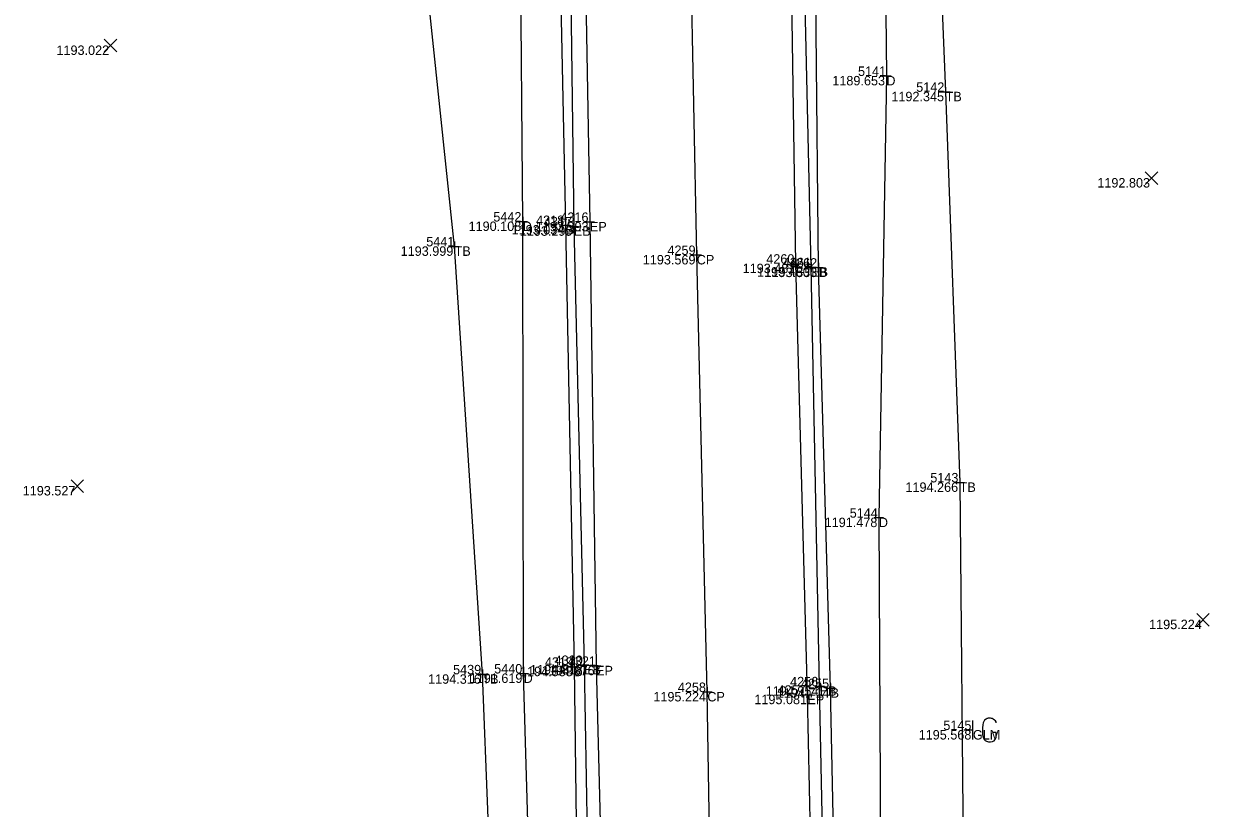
# Model space of a CAD drawing. Extents: x 2044996 to 2050343, y 455232 to 458054.
# Drawn here: x 2047545.2 to 2047670.6, y 457700.8 to 457783.9 of the extents above; entities that cross this region are included whole.
import ezdxf

# ---------------------------------------------------------------- set-up
doc = ezdxf.new("R2010")
doc.units = 0
for name, color, linetype in [('DR_X_Ditch', 7, 'Continuous'), ('DT_X_Contour_Minor', 7, 'Continuous'), ('DT_X_Contour_Text', 7, 'Continuous'), ('DT_X_Spot_Elev', 7, 'Continuous'), ('DT_X_Triangles', 7, 'Continuous'), ('DT_X_Void', 7, 'Continuous'), ('PV_X_COP', 7, 'Continuous'), ('PV_X_EOP', 7, 'Continuous'), ('PV_X_Shoulder_Aggregate', 7, 'Continuous'), ('SV_X_Break_Lines', 7, 'Continuous'), ('SV_X_Top_of_Bank', 7, 'Continuous'), ('UT_X_Gas_Cells', 7, 'Continuous')]:
    doc.layers.add(name, color=color, linetype=linetype)

msp = doc.modelspace()

# ---------------------------------------------------------------- linework, layer by layer
at = {"layer": 'DR_X_Ditch'}
for points in [[(2047603.88, 457240.71), (2047604.35, 457290.98), (2047605.27, 457322.96), (2047604.86, 457368.19), (2047603.19, 457417.51), (2047602.95, 457459.42), (2047602.66, 457501.84), (2047602.14, 457544.04), (2047601.08, 457584.06), (2047599.69, 457624.96), (2047599.4, 457669.27), (2047598.07, 457715.09), (2047597.97, 457762.92), (2047597.74, 457792.66), (2047596.26, 457838.2), (2047595.41, 457854.46)], [(2047635.93, 457828.45), (2047636.46, 457778.33), (2047635.67, 457731.58), (2047635.87, 457688.92), (2047636.59, 457650.58), (2047637.14, 457615.31), (2047638.36, 457574.87), (2047638.82, 457526.07), (2047639.21, 457482.92), (2047639.9, 457443.66), (2047641.24, 457398.66), (2047642.28, 457344.51), (2047644.03, 457300.89), (2047646.18, 457262.24), (2047646.96, 457237.04), (2047650.76, 457191.22), (2047650.42, 457143.89), (2047649.26, 457104.81), (2047651.9, 457052.9), (2047656.34, 457022.85)]]:
    msp.add_lwpolyline(points, dxfattribs=at)
at = {"layer": 'DT_X_Spot_Elev'}
for p, q in [((2047553.68, 457780.88), (2047555.02, 457782.22)), ((2047553.68, 457782.22), (2047555.02, 457780.88)), ((2047663.85, 457766.85), (2047665.18, 457768.19)), ((2047663.85, 457768.19), (2047665.18, 457766.85)), ((2047550.16, 457734.26), (2047551.5, 457735.6)), ((2047550.16, 457735.6), (2047551.5, 457734.26)), ((2047669.31, 457720.11), (2047670.64, 457721.45)), ((2047669.31, 457721.45), (2047670.64, 457720.11))]:
    msp.add_line(p, q, dxfattribs=at)
at = {"layer": 'DT_X_Void'}
for p, q in [((2047635.96, 457778.33), (2047636.96, 457778.33)), ((2047636.46, 457778.83), (2047636.46, 457777.83)), ((2047636.46, 457778.33), (2047636.46, 457778.33)), ((2047642.73, 457777.15), (2047642.73, 457776.15)), ((2047642.23, 457776.65), (2047643.23, 457776.65)), ((2047642.73, 457776.65), (2047642.73, 457776.65)), ((2047597.97, 457763.42), (2047597.97, 457762.42)), ((2047605.08, 457763.38), (2047605.08, 457762.38)), ((2047597.47, 457762.92), (2047598.47, 457762.92)), ((2047597.97, 457762.92), (2047597.97, 457762.92)), ((2047602.01, 457762.55), (2047603.01, 457762.55)), ((2047602.51, 457763.05), (2047602.51, 457762.05)), ((2047602.51, 457762.55), (2047602.51, 457762.55)), ((2047602.87, 457762.41), (2047603.87, 457762.41)), ((2047603.37, 457762.91), (2047603.37, 457761.91)), ((2047603.37, 457762.41), (2047603.37, 457762.41)), ((2047604.58, 457762.88), (2047605.58, 457762.88)), ((2047605.08, 457762.88), (2047605.08, 457762.88)), ((2047590.76, 457760.79), (2047590.76, 457759.79)), ((2047590.26, 457760.29), (2047591.26, 457760.29)), ((2047590.76, 457760.29), (2047590.76, 457760.29)), ((2047616.39, 457759.88), (2047616.39, 457758.88)), ((2047615.89, 457759.38), (2047616.89, 457759.38)), ((2047616.39, 457759.38), (2047616.39, 457759.38)), ((2047626.37, 457758.46), (2047627.37, 457758.46)), ((2047626.87, 457758.96), (2047626.87, 457757.96)), ((2047626.87, 457758.46), (2047626.87, 457758.46)), ((2047628.5, 457758.59), (2047628.5, 457757.59)), ((2047629.28, 457758.54), (2047629.28, 457757.54)), ((2047628, 457758.09), (2047629, 457758.09)), ((2047628.5, 457758.09), (2047628.5, 457758.09)), ((2047628.78, 457758.04), (2047629.78, 457758.04)), ((2047629.28, 457758.04), (2047629.28, 457758.04)), ((2047644.22, 457735.81), (2047644.22, 457734.81)), ((2047643.72, 457735.31), (2047644.72, 457735.31)), ((2047644.22, 457735.31), (2047644.22, 457735.31)), ((2047635.67, 457732.08), (2047635.67, 457731.08)), ((2047635.17, 457731.58), (2047636.17, 457731.58)), ((2047635.67, 457731.58), (2047635.67, 457731.58)), ((2047598.07, 457715.59), (2047598.07, 457714.59)), ((2047602.92, 457715.8), (2047603.92, 457715.8)), ((2047603.42, 457716.3), (2047603.42, 457715.3)), ((2047603.42, 457715.8), (2047603.42, 457715.8)), ((2047603.97, 457715.99), (2047604.97, 457715.99)), ((2047604.47, 457716.49), (2047604.47, 457715.49)), ((2047604.47, 457715.99), (2047604.47, 457715.99)), ((2047605.24, 457715.9), (2047606.24, 457715.9)), ((2047605.74, 457716.4), (2047605.74, 457715.4)), ((2047605.74, 457715.9), (2047605.74, 457715.9)), ((2047593.2, 457715), (2047594.2, 457715)), ((2047593.7, 457715.5), (2047593.7, 457714.5)), ((2047593.7, 457715), (2047593.7, 457715)), ((2047597.57, 457715.09), (2047598.57, 457715.09)), ((2047598.07, 457715.09), (2047598.07, 457715.09)), ((2047617.01, 457713.13), (2047618.01, 457713.13)), ((2047617.51, 457713.63), (2047617.51, 457712.63)), ((2047617.51, 457713.13), (2047617.51, 457713.13)), ((2047628.1, 457713.34), (2047628.1, 457712.34)), ((2047628.9, 457713.73), (2047629.9, 457713.73)), ((2047629.4, 457714.23), (2047629.4, 457713.23)), ((2047629.4, 457713.73), (2047629.4, 457713.73)), ((2047630.06, 457713.53), (2047631.06, 457713.53)), ((2047630.56, 457714.03), (2047630.56, 457713.03)), ((2047630.56, 457713.53), (2047630.56, 457713.53)), ((2047627.6, 457712.84), (2047628.6, 457712.84)), ((2047628.1, 457712.84), (2047628.1, 457712.84))]:
    msp.add_line(p, q, dxfattribs=at)
at = {"layer": 'PV_X_COP'}
msp.add_lwpolyline([(2047630.7, 457032.77), (2047629.57, 457079.46), (2047628.83, 457121.31), (2047627.83, 457168.37), (2047627.23, 457213.89), (2047626.35, 457261.41), (2047625.27, 457313.88), (2047624.14, 457367.69), (2047623.14, 457414.96), (2047622.16, 457463.48), (2047621.21, 457510.6), (2047620.34, 457561.9), (2047619.47, 457614.83), (2047618.33, 457662.23), (2047617.51, 457713.13), (2047616.39, 457759.38), (2047615.44, 457807.27), (2047614.41, 457854.52), (2047614.29, 457881.56), (2047613.16, 457931.14), (2047612.06, 457984.05), (2047611.48, 458032.26), (2047610.91, 458052.26)], dxfattribs=at)
at = {"layer": 'PV_X_EOP'}
for p, q in [((2047626.87, 457758.46), (2047626.15, 457807.46)), ((2047604.32, 457806.33), (2047605.08, 457762.88)), ((2047605.08, 457762.88), (2047605.74, 457715.9)), ((2047628.1, 457712.84), (2047626.87, 457758.46)), ((2047605.74, 457715.9), (2047606.92, 457669.5)), ((2047629.22, 457661.11), (2047628.1, 457712.84))]:
    msp.add_line(p, q, dxfattribs=at)
at = {"layer": 'PV_X_Shoulder_Aggregate'}
for p, q in [((2047602.79, 457806.21), (2047603.37, 457762.41)), ((2047603.37, 457762.41), (2047604.47, 457715.99)), ((2047604.47, 457715.99), (2047605.27, 457669.2))]:
    msp.add_line(p, q, dxfattribs=at)
msp.add_lwpolyline([(2047636.93, 457312.89), (2047635.93, 457367.47), (2047634.97, 457414.6), (2047633.92, 457462.12), (2047633.13, 457509.72), (2047632.17, 457560.26), (2047631.16, 457614.81), (2047630.46, 457661.29), (2047629.4, 457713.73), (2047628.5, 457758.09), (2047627.36, 457807.43), (2047627.48, 457822.09), (2047628.61, 457825.87), (2047628.68, 457844.07), (2047627.2, 457879.15), (2047626.26, 457880.5), (2047625.13, 457929.52), (2047623.96, 457984.29), (2047622.9, 458032.45), (2047622.9, 458052.72)], dxfattribs=at)
at = {"layer": 'SV_X_Break_Lines'}
for points in [[(2047600.59, 457854.75), (2047601.57, 457806.15), (2047602.51, 457762.55), (2047603.42, 457715.8), (2047604.03, 457669.25), (2047604.95, 457623.23), (2047606.04, 457575.98), (2047606.89, 457528.52), (2047606.36, 457485.08), (2047608.62, 457438.46), (2047609.61, 457393.11), (2047610.32, 457343.26)], [(2047638.13, 457312.9), (2047637.8, 457367.1), (2047636.31, 457414.94), (2047635.39, 457462.19), (2047634.84, 457510.57), (2047633.75, 457560.46), (2047632.44, 457614.37), (2047631.64, 457661.27), (2047630.56, 457713.53), (2047629.28, 457758.04), (2047628.78, 457808.04), (2047629.36, 457824.93)]]:
    msp.add_lwpolyline(points, dxfattribs=at)
at = {"layer": 'SV_X_Top_of_Bank'}
for points in [[(2047602.07, 457232.89), (2047595.37, 457236.81), (2047596.56, 457240.43), (2047601.59, 457243.99), (2047601.86, 457291.34), (2047601.11, 457323.06), (2047599.87, 457367.88), (2047599.04, 457416.36), (2047598.26, 457460), (2047598.65, 457502.28), (2047597.03, 457543.46), (2047596.32, 457583.97), (2047595.27, 457626.15), (2047595.52, 457669.28), (2047593.7, 457715), (2047590.76, 457760.29), (2047587.57, 457790.55), (2047585.9, 457853.96)], [(2047640.57, 457829.63), (2047642.73, 457776.65), (2047644.22, 457735.31), (2047644.62, 457692.67), (2047644.93, 457653.27), (2047648.25, 457619.87), (2047649.32, 457574.48), (2047650.08, 457529.2), (2047650.6, 457480.31), (2047651.65, 457447.12), (2047652.29, 457398.02), (2047653.83, 457346.33), (2047654.34, 457298.99), (2047654.68, 457261.41), (2047656.79, 457189.89), (2047656.98, 457146.62), (2047657.59, 457104.22), (2047658.54, 457057.89), (2047659.73, 457026.44)]]:
    msp.add_lwpolyline(points, dxfattribs=at)
at = {"layer": 'UT_X_Gas_Cells'}
for p, q in [((2047645.62, 457708.1), (2047645.62, 457710.1)), ((2047645.62, 457709.1), (2047644.67, 457709.1))]:
    msp.add_line(p, q, dxfattribs=at)
msp.add_lwpolyline([(2047648.09, 457709.86), (2047648.07, 457709.96), (2047648.01, 457710.06), (2047647.92, 457710.15), (2047647.78, 457710.27), (2047647.68, 457710.31), (2047647.6, 457710.33), (2047647.48, 457710.35), (2047647.25, 457710.35), (2047647.15, 457710.33), (2047647.09, 457710.31), (2047647.01, 457710.27), (2047646.85, 457710.15), (2047646.76, 457710.02), (2047646.7, 457709.86), (2047646.66, 457709.64), (2047646.62, 457709.33), (2047646.62, 457708.91), (2047646.64, 457708.58), (2047646.72, 457708.32), (2047646.83, 457708.09), (2047646.93, 457708.01), (2047647.05, 457707.93), (2047647.27, 457707.85), (2047647.48, 457707.85), (2047647.7, 457707.89), (2047647.78, 457707.93), (2047647.86, 457707.97), (2047647.94, 457708.05), (2047648.01, 457708.17), (2047648.09, 457708.34), (2047648.09, 457708.84), (2047647.68, 457708.84)], dxfattribs=at)

# ---------------------------------------------------------------- texts
at = {"layer": 'DT_X_Contour_Minor'}
for s, p in [('1193.022', (2047548.62, 457780.55)), ('1189.653', (2047630.74, 457777.33)), ('1192.345', (2047636.99, 457775.65)), ('1192.803', (2047658.79, 457766.52)), ('1190.108', (2047592.24, 457761.92)), ('1193.034', (2047596.8, 457761.55)), ('1193.299', (2047597.66, 457761.41)), ('1193.393', (2047599.36, 457761.88)), ('1193.999', (2047585.05, 457759.29)), ('1193.569', (2047610.68, 457758.38)), ('1193.481', (2047621.25, 457757.46)), ('1193.460', (2047622.77, 457757.09)), ('1193.333', (2047623.56, 457757.04)), ('1193.527', (2047545.05, 457733.93)), ('1194.266', (2047638.48, 457734.31)), ('1191.478', (2047629.93, 457730.58)), ('1195.224', (2047664.27, 457719.78)), ('1194.588', (2047597.69, 457714.8)), ('1194.818', (2047598.74, 457714.99)), ('1194.876', (2047600, 457714.9)), ('1194.316', (2047587.96, 457714)), ('1191.619', (2047592.36, 457714.09)), ('1195.224', (2047611.8, 457712.13)), ('1194.954', (2047623.69, 457712.73)), ('1194.714', (2047624.86, 457712.53)), ('1195.081', (2047622.49, 457711.84)), ('1195.568', (2047639.88, 457708.1))]:
    msp.add_text(s, height=1, dxfattribs=at).set_placement(p)
at = {"layer": 'DT_X_Contour_Text'}
for s, p in [('D', (2047636.46, 457777.33)), ('TB', (2047642.73, 457775.65)), ('D', (2047597.97, 457761.92)), ('B', (2047602.51, 457761.55)), ('EB', (2047603.37, 457761.41)), ('EP', (2047605.08, 457761.88)), ('TB', (2047590.76, 457759.29)), ('CP', (2047616.39, 457758.38)), ('EP', (2047626.87, 457757.46)), ('EB', (2047628.5, 457757.09)), ('B', (2047629.28, 457757.04)), ('TB', (2047644.22, 457734.31)), ('D', (2047635.67, 457730.58)), ('B', (2047603.42, 457714.8)), ('EB', (2047604.47, 457714.99)), ('EP', (2047605.74, 457714.9)), ('TB', (2047593.7, 457714)), ('D', (2047598.07, 457714.09)), ('CP', (2047617.51, 457712.13)), ('EB', (2047629.4, 457712.73)), ('B', (2047630.56, 457712.53)), ('EP', (2047628.1, 457711.84)), ('GLM', (2047645.62, 457708.1))]:
    msp.add_text(s, height=1, dxfattribs=at).set_placement(p)
at = {"layer": 'DT_X_Triangles'}
for s, p in [('5141', (2047633.46, 457778.33)), ('5142', (2047639.62, 457776.65)), ('5442', (2047594.86, 457762.92)), ('4318', (2047599.39, 457762.55)), ('4317', (2047600.21, 457762.41)), ('4316', (2047601.96, 457762.88)), ('5441', (2047587.76, 457760.29)), ('4259', (2047613.29, 457759.38)), ('4260', (2047623.75, 457758.46)), ('4261', (2047625.5, 457758.09)), ('4262', (2047626.16, 457758.04)), ('5143', (2047641.11, 457735.31)), ('5144', (2047632.58, 457731.58)), ('4319', (2047600.32, 457715.8)), ('4320', (2047601.35, 457715.99)), ('4321', (2047602.74, 457715.9)), ('5439', (2047590.6, 457715)), ('5440', (2047594.95, 457715.09)), ('4256', (2047626.27, 457713.73)), ('4255', (2047627.43, 457713.53)), ('4258', (2047614.39, 457713.13)), ('4257', (2047624.94, 457712.84)), ('5145', (2047642.49, 457709.1))]:
    msp.add_text(s, height=1, dxfattribs=at).set_placement(p)

doc.saveas('drawing.dxf')
